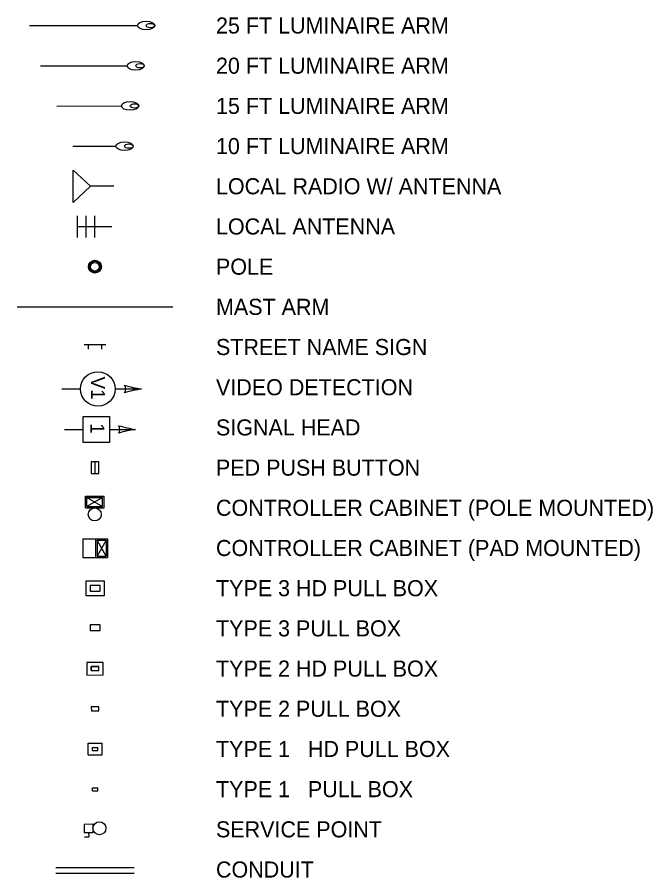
# Model space of a CAD drawing. Extents: x 993729 to 994927, y 1984823 to 1986420.
# Drawn here: x 994063.9 to 994211, y 1986220.6 to 1986419.7 of the extents above; entities that cross this region are included whole.
import ezdxf

# ---------------------------------------------------------------- set-up
doc = ezdxf.new("R2010")
doc.units = 0
for name, color, linetype in [('EX_BREAKLINE', 7, 'Continuous'), ('EX_BREAKLINE_PT_SYM', 7, 'Continuous'), ('EX_FLAG_POLE', 7, 'Continuous'), ('EX_LANDSCAPING', 7, 'Continuous'), ('EX_MSC_PT_SYM', 7, 'Continuous'), ('EX_SANITARY_SEWER', 7, 'Continuous'), ('EX_SIGN', 7, 'Continuous'), ('EX_STORM_SEWER', 7, 'Continuous'), ('EX_WALL', 7, 'Continuous')]:
    doc.layers.add(name, color=color, linetype=linetype)

msp = doc.modelspace()

# ---------------------------------------------------------------- linework, layer by layer
at = {"layer": 'EX_BREAKLINE'}
msp.add_lwpolyline([(994081.01, 1986316.78), (994081, 1986314.14), (994081.88, 1986314.14), (994081.88, 1986316.78)], close=True, dxfattribs=at)
at = {"layer": 'EX_BREAKLINE_PT_SYM'}
for p, q in [((994074.2, 1986333.67), (994078.53, 1986333.67)), ((994086.53, 1986333.67), (994092.6, 1986333.68)), ((994074.8, 1986324.29), (994079.14, 1986324.29)), ((994085.21, 1986324.31), (994091.25, 1986324.32))]:
    msp.add_line(p, q, dxfattribs=at)
msp.add_lwpolyline([(994079.15, 1986321.27), (994079.14, 1986327.34), (994085.21, 1986327.34), (994085.21, 1986321.27)], close=True, dxfattribs=at)
msp.add_circle((994082.53, 1986333.67), 4, dxfattribs=at)
for centre, radius, start, end in [((994087.33, 1986333.67), 1.63, 328.1778, 31.8725), ((994097, 1986362.82), 29.47, 253.6787, 261.4168), ((994097.02, 1986304.54), 29.47, 98.6335, 106.3716), ((994085.98, 1986324.31), 1.63, 328.1778, 31.8725), ((994095.65, 1986353.46), 29.47, 253.6787, 261.4168), ((994095.67, 1986295.18), 29.47, 98.6335, 106.3716)]:
    msp.add_arc(centre, radius, start, end, dxfattribs=at)
at = {"layer": 'EX_FLAG_POLE'}
for p, q in [((994079.39, 1986233.01), (994081.39, 1986233.02)), ((994079.39, 1986233.01), (994079.39, 1986231.01)), ((994081.39, 1986233.02), (994081.39, 1986231.02)), ((994079.39, 1986231.01), (994081.39, 1986231.02)), ((994080.39, 1986231.01), (994080.4, 1986230.01)), ((994079.4, 1986230.01), (994080.4, 1986230.01)), ((994072.83, 1986222.95), (994090.96, 1986222.96)), ((994072.83, 1986221.63), (994090.96, 1986221.63))]:
    msp.add_line(p, q, dxfattribs=at)
msp.add_circle((994082.89, 1986232.02), 1.5, dxfattribs=at)
at = {"layer": 'EX_LANDSCAPING'}
for p, q in [((994084.05, 1986289.19), (994079.72, 1986289.19)), ((994079.72, 1986289.19), (994079.72, 1986285.92)), ((994084.05, 1986285.92), (994084.05, 1986289.19)), ((994080.72, 1986288.19), (994080.72, 1986286.92)), ((994083.05, 1986288.19), (994080.72, 1986288.19)), ((994080.72, 1986286.92), (994083.05, 1986286.92)), ((994083.05, 1986286.92), (994083.05, 1986288.19)), ((994079.72, 1986285.92), (994084.05, 1986285.92)), ((994080.71, 1986279.07), (994080.72, 1986277.8)), ((994083.05, 1986279.07), (994080.71, 1986279.07)), ((994083.05, 1986277.8), (994083.05, 1986279.07)), ((994080.72, 1986277.8), (994083.05, 1986277.8)), ((994083.76, 1986270.42), (994080.01, 1986270.41)), ((994080.01, 1986270.41), (994080.01, 1986267.49)), ((994083.76, 1986267.5), (994083.76, 1986270.42)), ((994081.01, 1986268.5), (994081.01, 1986269.42)), ((994081.01, 1986269.42), (994082.76, 1986269.42)), ((994081.01, 1986269.42), (994081.01, 1986268.5)), ((994082.76, 1986269.42), (994081.01, 1986269.42)), ((994081.01, 1986268.5), (994082.76, 1986268.5)), ((994081.01, 1986268.5), (994082.76, 1986268.5)), ((994082.76, 1986268.5), (994082.76, 1986269.42)), ((994082.76, 1986268.5), (994082.76, 1986269.42)), ((994080.01, 1986267.49), (994083.76, 1986267.5)), ((994081.01, 1986260.12), (994081.02, 1986259.2)), ((994082.76, 1986260.12), (994081.01, 1986260.12)), ((994081.02, 1986259.2), (994082.77, 1986259.2)), ((994082.77, 1986259.2), (994082.76, 1986260.12))]:
    msp.add_line(p, q, dxfattribs=at)
msp.add_lwpolyline([(994081, 1986314.14), (994082.75, 1986314.14), (994082.75, 1986316.78), (994081.01, 1986316.78)], close=True, dxfattribs=at)
at = {"layer": 'EX_MSC_PT_SYM'}
msp.add_line((994063.85, 1986352.66), (994099.85, 1986352.67), dxfattribs=at)
for radius in [1.5, 1.25, 1]:
    msp.add_circle((994081.85, 1986361.97), radius, dxfattribs=at)
at = {"layer": 'EX_SANITARY_SEWER'}
for p, q in [((994066.68, 1986417.75), (994091.68, 1986417.76)), ((994069.28, 1986408.45), (994089.28, 1986408.46)), ((994072.99, 1986399.15), (994087.99, 1986399.16)), ((994076.71, 1986389.85), (994086.71, 1986389.86)), ((994076.84, 1986376.84), (994076.84, 1986384.34)), ((994076.84, 1986384.34), (994080.84, 1986380.59)), ((994080.84, 1986380.59), (994076.84, 1986376.84)), ((994086.19, 1986380.59), (994080.84, 1986380.59)), ((994077.77, 1986373.75), (994077.77, 1986368.75)), ((994079.77, 1986373.75), (994079.77, 1986368.75)), ((994081.77, 1986373.75), (994081.77, 1986368.75)), ((994077.77, 1986371.25), (994085.77, 1986371.25)), ((994079.63, 1986306.14), (994079.63, 1986308.88)), ((994079.63, 1986308.88), (994083.96, 1986308.88)), ((994079.96, 1986308.55), (994083.63, 1986308.55)), ((994079.96, 1986306.47), (994079.96, 1986308.55)), ((994083.63, 1986308.55), (994079.96, 1986306.47)), ((994079.98, 1986308.55), (994083.63, 1986306.47)), ((994083.63, 1986306.47), (994083.63, 1986308.55)), ((994083.96, 1986306.14), (994083.96, 1986308.88)), ((994079.96, 1986306.47), (994083.63, 1986306.47)), ((994079.63, 1986306.14), (994083.96, 1986306.14)), ((994080.3, 1986251.72), (994083.49, 1986251.72)), ((994080.3, 1986248.99), (994080.3, 1986251.72)), ((994081.3, 1986249.99), (994081.3, 1986250.72)), ((994081.3, 1986250.72), (994082.49, 1986250.72)), ((994082.49, 1986249.99), (994082.49, 1986250.72)), ((994083.49, 1986248.99), (994083.49, 1986251.72)), ((994080.3, 1986248.99), (994083.49, 1986248.99)), ((994081.3, 1986249.99), (994082.49, 1986249.99)), ((994081.3, 1986240.69), (994081.3, 1986241.42)), ((994081.3, 1986241.42), (994082.49, 1986241.42)), ((994081.3, 1986240.69), (994082.49, 1986240.69)), ((994082.49, 1986240.69), (994082.49, 1986241.42))]:
    msp.add_line(p, q, dxfattribs=at)
msp.add_circle((994081.8, 1986304.64), 1.5, dxfattribs=at)
for centre, major_axis in [((994093.68, 1986417.76), (2, 0)), ((994094.68, 1986417.76), (-1, 0)), ((994091.28, 1986408.46), (2, 0)), ((994092.28, 1986408.46), (-1, 0)), ((994089.99, 1986399.16), (2, 0)), ((994090.99, 1986399.16), (-1, 0)), ((994088.71, 1986389.86), (2, 0)), ((994089.71, 1986389.86), (-1, 0))]:
    msp.add_ellipse(centre, major_axis=major_axis, ratio=0.5, dxfattribs=at)
at = {"layer": 'EX_STORM_SEWER'}
for p, q in [((994079.01, 1986299.02), (994084.75, 1986299.02)), ((994079.01, 1986299.02), (994079.01, 1986294.69)), ((994082.01, 1986299.02), (994082.01, 1986294.69)), ((994082.34, 1986298.69), (994082.34, 1986295.02)), ((994084.42, 1986295.02), (994082.34, 1986298.69)), ((994082.34, 1986298.69), (994084.42, 1986298.69)), ((994084.42, 1986298.67), (994082.34, 1986295.02)), ((994084.42, 1986298.69), (994084.42, 1986295.02)), ((994084.75, 1986299.02), (994084.75, 1986294.69)), ((994079.01, 1986294.69), (994084.75, 1986294.69)), ((994082.34, 1986295.02), (994084.42, 1986295.02))]:
    msp.add_line(p, q, dxfattribs=at)
at = {"layer": 'EX_WALL'}
for p, q in [((994084.36, 1986343.86), (994079.36, 1986343.86)), ((994080.36, 1986342.86), (994080.36, 1986343.86)), ((994083.36, 1986343.86), (994083.36, 1986342.86)), ((994084.36, 1986343.86), (994083.36, 1986343.86))]:
    msp.add_line(p, q, dxfattribs=at)

# ---------------------------------------------------------------- texts
at = {"layer": 'EX_BREAKLINE_PT_SYM'}
for s, p in [('V1', (994080.94, 1986336.55)), ('1', (994080.8, 1986325.77))]:
    msp.add_text(s, height=3.25, rotation=270.0252, dxfattribs=at).set_placement(p)
at = {"layer": 'EX_SIGN'}
for s, p in [('25 FT LUMINAIRE ARM', (994109.87, 1986415.92)), ('20 FT LUMINAIRE ARM', (994109.87, 1986406.62)), ('15 FT LUMINAIRE ARM', (994109.87, 1986397.32)), ('10 FT LUMINAIRE ARM', (994109.87, 1986388.02)), ('LOCAL RADIO W/ ANTENNA', (994109.87, 1986378.72)), ('LOCAL ANTENNA', (994109.87, 1986369.42)), ('POLE', (994109.87, 1986360.12)), ('MAST ARM', (994109.87, 1986350.82)), ('STREET NAME SIGN', (994109.87, 1986341.52)), ('VIDEO DETECTION', (994109.87, 1986332.22)), ('SIGNAL HEAD', (994109.87, 1986322.92)), ('PED PUSH BUTTON', (994109.87, 1986313.62)), ('CONTROLLER CABINET (POLE MOUNTED)', (994109.87, 1986304.32)), ('CONTROLLER CABINET (PAD MOUNTED)', (994109.87, 1986295.02)), ('TYPE 3 HD PULL BOX', (994109.87, 1986285.72)), ('TYPE 3 PULL BOX', (994109.87, 1986276.42)), ('TYPE 2 HD PULL BOX', (994109.87, 1986267.12)), ('TYPE 2 PULL BOX', (994109.87, 1986257.82)), ('TYPE 1   HD PULL BOX', (994109.87, 1986248.52)), ('TYPE 1   PULL BOX', (994109.87, 1986239.22)), ('SERVICE POINT', (994109.87, 1986229.92)), ('CONDUIT', (994109.87, 1986220.62))]:
    msp.add_text(s, height=3.72, dxfattribs=at).set_placement(p)

doc.saveas('drawing.dxf')
